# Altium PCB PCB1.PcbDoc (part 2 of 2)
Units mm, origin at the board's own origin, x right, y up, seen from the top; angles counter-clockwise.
Board outline 84 x 60 mm, 2 copper layers (Top Layer, Bottom Layer); 61 components, 46 nets, 218 pads, 307 vias.
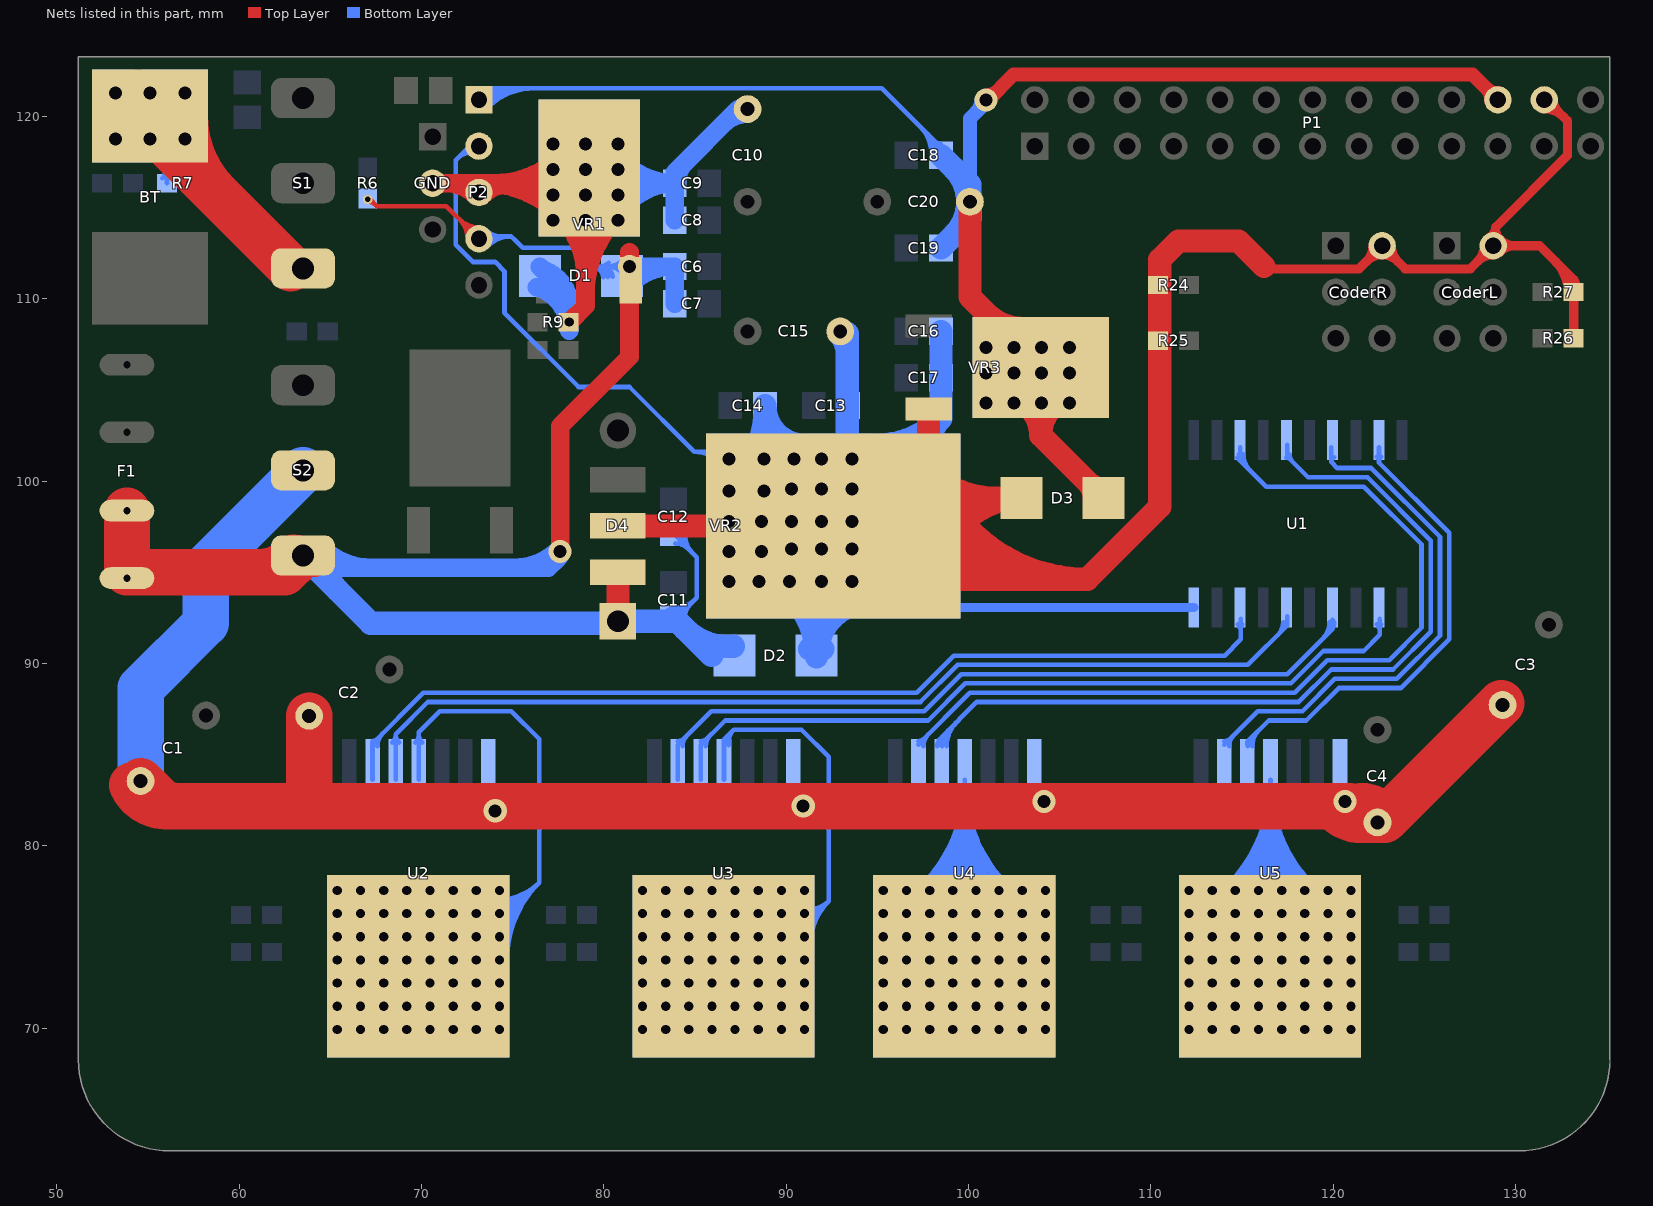
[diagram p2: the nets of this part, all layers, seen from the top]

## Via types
v1: diameter 0.762, hole 0.508, Top Layer to Bottom Layer, 224 vias
v2: diameter 1.27, hole 0.711, Top Layer to Bottom Layer, 75 vias
v3: diameter 0.559, hole 0.305, Top Layer to Bottom Layer, 3 vias
v4: diameter 0.508, hole 0.305, Top Layer to Bottom Layer, 3 vias
v5: diameter 1, hole 0.5, Top Layer to Bottom Layer, 2 vias

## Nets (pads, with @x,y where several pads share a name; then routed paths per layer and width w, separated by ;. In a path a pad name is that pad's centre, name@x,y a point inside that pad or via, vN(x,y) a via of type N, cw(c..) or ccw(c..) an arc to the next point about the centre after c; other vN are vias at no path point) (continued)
NetU1_3: U1.3 U4.2 | length 49.7
  Bottom Layer w0.254: U4.2@97.257,85.533 97.257,85.573 100.076,88.392 117.896,88.392 119.674,90.17 123.067,90.17 124.841,91.944 124.841,96.524 121.67,99.695 116.332,99.695 U1.3@114.745,101.282 ; U4.2@97.257,85.737 ccw(c97.257,86.133) U4.2@97.537,85.853 ; U4.2@97.53,85.464 cw(c98.451,85.464) 97.8,86.116 ; U1.3@114.811,101.458 ccw(c115.395,101.458) 114.982,101.045 ; U1.3@114.892,101.516 U1.3@114.892,101.854 ; U1.3@115.065,101.458 ccw(c116.262,101.458) 115.416,100.611
NetU1_5: U1.5 U4.3 | length 48.6
  Bottom Layer w0.254: U4.3@98.292,85.464 cw(c98.907,85.464) 98.472,85.899 ; U4.3@98.527,85.533 98.527,85.954 100.457,87.884 118.106,87.884 119.884,89.662 123.277,89.662 125.349,91.734 125.349,96.734 121.88,100.203 118.618,100.203 117.475,101.346 U1.5@117.475,101.981 ; U4.3@98.546,85.464 cw(c99.774,85.464) 98.905,86.332 ; U4.3@98.8,85.464 cw(c100.641,85.464) 99.339,86.766 ; U1.5@117.432,101.285 cw(c117.432,101.034) U1.5@117.61,101.211 ; U1.5@117.605,101.458 ccw(c118.189,101.458) 117.776,101.045
NetU1_7: U1.7 U5.2 | length 29.6
  Bottom Layer w0.254: U5.2@114.021,85.533 115.864,87.376 118.317,87.376 120.095,89.154 123.488,89.154 125.857,91.523 125.857,96.945 122.091,100.711 120.225,100.711 119.888,101.048 U1.7@119.888,101.854 ; U5.2@114.021,85.737 ccw(c114.021,86.23) 114.369,85.881 ; U5.2@114.294,85.464 cw(c115.119,85.464) 114.535,86.047 ; 119.888,101.04 cw(c120.184,101.04) U1.7@120.05,101.304
NetU1_9: U1.9 U5.3 | length 27.8
  Bottom Layer w0.254: U5.3@115.291,85.533 115.291,85.7 116.459,86.868 118.527,86.868 120.305,88.646 123.698,88.646 126.365,91.313 126.365,97.155 122.512,101.008 U1.9@122.512,101.854 ; U5.3@115.31,85.464 cw(c115.925,85.464) 115.49,85.899 ; U5.3@115.564,85.464 cw(c116.792,85.464) 115.923,86.332 ; U1.9@122.39,101.336 cw(c122.094,101.04) 122.512,101.04 cw(c122.93,101.04) U1.9@122.634,101.336
NetU1_12: U1.12 U3.3 | length 44.5
  Bottom Layer w0.254: U3.3@85.319,83.614 85.319,85.533 86.654,86.868 92.075,86.868 ; U3.3@85.319,85.737 ccw(c85.319,86.23) 85.667,85.881 ; U3.3@85.592,85.464 cw(c86.417,85.464) 85.833,86.047 ; 92.329,86.868 92.075,86.868 ; U1.12@122.39,92.136 cw(c121.991,91.737) 122.555,91.737 ; 122.555,91.944 cw(c122.826,91.944) U1.12@122.634,92.136 ; U1.12@122.555,92.456 122.555,91.567 121.666,90.678 119.463,90.678 117.685,88.9 99.818,88.9 97.786,86.868 92.075,86.868
NetU1_14: U1.14 U3.2 | length 43.8
  Bottom Layer w0.254: U3.2@84.049,83.614 84.049,85.533 85.892,87.376 91.059,87.376 ; U3.2@84.049,85.737 ccw(c84.049,86.23) 84.397,85.881 ; U3.2@84.322,85.464 cw(c85.147,85.464) 84.563,86.047 ; 91.313,87.376 91.059,87.376 ; 119.427,91.36 ccw(c118.529,92.258) U1.14@119.799,92.258 ; 119.861,91.794 ccw(c119.396,92.258) U1.14@120.053,92.258 ; U1.14@119.963,92.381 119.963,91.896 117.475,89.408 99.608,89.408 97.576,87.376 91.059,87.376
NetU1_16: U1.16 U2.3 | length 56.1
  Bottom Layer w0.254: U2.3@68.396,85.659 ccw(c67.952,86.113) 68.587,86.113 ; U2.3@68.587,83.614 68.587,86.113 ; U2.3@68.777,85.659 cw(c69.221,86.113) 68.587,86.113 ; 116.977,91.577 ccw(c116.296,92.258) U1.16@117.259,92.258 ; U1.16@117.475,92.583 117.475,92.075 115.316,89.916 99.397,89.916 97.365,87.884 70.358,87.884 68.587,86.113
NetU1_18: U1.18 U2.2 | length 54.8
  Bottom Layer w0.254: U2.2@67.317,83.614 67.317,85.605 70.104,88.392 97.155,88.392 99.187,90.424 114.046,90.424 114.935,91.313 U1.18@114.935,92.456 ; U2.2@67.317,85.737 ccw(c67.317,86.056) U2.2@67.542,85.83 ; U2.2@67.59,85.464 cw(c68.589,85.464) 67.882,86.17 ; U1.18@114.77,92.136 cw(c114.371,91.737) 114.935,91.737 ; 114.935,91.944 cw(c115.206,91.944) U1.18@115.014,92.136
NetU2_4: U2.0 U2.4 U2.8 | length 96.3
  Bottom Layer w0.254: U2.4@69.664,85.657 ccw(c69.213,86.107) 69.85,86.107 ; 69.85,86.139 ccw(c70.532,86.139) U2.4@70.05,85.657 ; U2.4@69.857,83.614 69.85,83.62 69.85,86.233 70.993,87.376 74.93,87.376 76.454,85.852 76.454,77.978 ; U2.8@71.202,75.578 ccw(c72.58,77.786) U2.8@74.421,75.945 ; U2.8@71.336,75.793 ccw(c72.754,78.064) U2.8@74.647,76.171 ; U2.8@71.471,76.009 ccw(c72.928,78.342) 74.873,76.397 ; U2.8@71.605,76.224 ccw(c73.101,78.62) 75.099,76.623 ; U2.8@71.74,76.44 ccw(c73.275,78.898) 75.325,76.849 ; U2.8@71.874,76.655 ccw(c73.449,79.176) 75.55,77.074 ; U2.8@72.009,76.87 ccw(c73.622,79.454) 75.776,77.3 ; U2.8@72.143,77.086 ccw(c73.796,79.732) 76.002,77.526 ; U2.8@72.278,77.301 ccw(c73.97,80.01) 76.228,77.752 ; U2.8@72.412,77.517 ccw(c74.143,80.288) 76.454,77.978 ; U2.8@72.517,74.041 76.454,77.978 ; U2.8@72.755,74.279 ccw(c72.439,74.595) U2.8@72.801,74.857 ; U2.8@72.965,74.489 ccw(c72.683,74.772) v1(73.006,75.006) ccw(c73.006,76.155) U2.8@73.819,75.343 ; U2.8@73.006,74.752 ccw(c73.006,75.288) U2.8@73.385,74.909 ; U2.8@73.006,75.26 ccw(c73.006,77.023) U2.8@74.252,75.776 ; U2.8@73.432,73.502 cw(c76.681,73.608) U2.8@74.382,75.906 ; U2.8@73.506,75.03 ccw(c72.26,76.276) U2.8@74.022,76.276 ; U2.8@73.686,73.51 cw(c77.483,73.635) U2.8@74.797,76.321 ; U2.8@73.94,73.518 cw(c78.285,73.661) 75.211,76.735 ; U2.8@73.94,75.464 ccw(c73.127,76.276) v1(74.276,76.276) ccw(c74.276,77.425) 75.089,76.613 ; U2.8@74.194,73.527 cw(c79.087,73.687) 75.625,77.149 ; U2.8@74.276,76.022 ccw(c74.276,76.558) U2.8@74.655,76.179 ; U2.8@74.276,76.53 ccw(c74.276,78.293) 75.522,77.046 ; U2.8@74.373,75.897 ccw(c73.994,76.276) U2.8@74.53,76.276 ; U2.8@74.448,73.535 cw(c79.889,73.714) 76.039,77.563 ; U2.8@74.702,73.543 cw(c80.692,73.74) 76.454,77.978
  other v1: 65.386,69.926 66.656,69.926 67.926,69.926 69.196,69.926 70.466,69.926 71.736,69.926 73.006,69.926 74.276,69.926 65.386,71.196 66.656,71.196 67.926,71.196 69.196,71.196 70.466,71.196 71.736,71.196 73.006,71.196 74.276,71.196 65.386,72.466 66.656,72.466 67.926,72.466 69.196,72.466 70.466,72.466 71.736,72.466 73.006,72.466 74.276,72.466 65.386,73.736 66.656,73.736 67.926,73.736 69.196,73.736 70.466,73.736 71.736,73.736 73.006,73.736 74.276,73.736 65.386,75.006 66.656,75.006 67.926,75.006 69.196,75.006 70.466,75.006 71.736,75.006 74.276,75.006 65.386,76.276 66.656,76.276 67.926,76.276 69.196,76.276 70.466,76.276 71.736,76.276 73.006,76.276 65.386,77.546 66.656,77.546 67.926,77.546 69.196,77.546 70.466,77.546 71.736,77.546 73.006,77.546 74.276,77.546
NetU3_4: U3.0 U3.4 U3.8 | length 70.7
  Bottom Layer w0.254: U3.4@86.589,83.614 86.589,85.827 87.122,86.36 ; U3.4@86.607,85.467 cw(c87.218,85.578) 86.779,86.017 ; U3.4@86.857,85.513 cw(c87.798,85.684) 87.122,86.36 ; U3.8@88.688,75.634 ccw(c89.844,76.859) U3.8@91.035,75.668 ; U3.8@88.862,75.819 ccw(c90.024,77.049) U3.8@91.22,75.853 ; U3.8@89.037,76.004 ccw(c90.203,77.239) U3.8@91.405,76.038 ; U3.8@89.211,76.188 ccw(c90.383,77.429) 91.589,76.222 ; U3.8@89.385,76.373 ccw(c90.562,77.62) 91.774,76.407 ; U3.8@89.56,76.558 ccw(c90.742,77.81) 91.959,76.592 ; U3.8@89.662,74.295 92.329,76.962 ; U3.8@89.734,76.742 ccw(c90.921,78) 92.144,76.777 ; U3.8@89.738,74.498 ccw(c89.738,74.805) U3.8@89.955,74.588 ; U3.8@89.738,74.752 ccw(c89.738,75.672) U3.8@90.389,75.022 ; v1(89.738,75.006) ccw(c89.738,76.539) U3.8@90.822,75.455 ; U3.8@89.738,75.26 ccw(c89.738,77.406) U3.8@91.256,75.889 ; U3.8@89.908,76.927 ccw(c91.101,78.19) 92.329,76.962 ; U3.8@89.924,74.557 cw(c91.008,73.473) v1(91.008,75.006) cw(c92.541,75.006) U3.8@91.457,76.09 ; U3.8@90.126,74.759 ccw(c88.608,76.276) U3.8@90.754,76.276 ; U3.8@90.358,74.991 cw(c91.008,74.34) U3.8@91.008,75.26 ; U3.8@90.5,75.006 cw(c90.807,75.006) U3.8@90.59,75.223 ; U3.8@90.559,75.192 ccw(c89.475,76.276) v1(91.008,76.276) ccw(c91.161,77.405) 91.966,76.599 ; U3.8@90.63,73.987 cw(c92.835,74.315) U3.8@91.259,75.892 ; U3.8@90.754,75.006 cw(c91.674,75.006) U3.8@91.024,75.657 ; U3.8@90.791,75.424 cw(c91.008,75.208) U3.8@91.008,75.514 ; U3.8@90.881,74.025 cw(c93.457,74.407) 91.615,76.248 ; U3.8@90.94,75.773 ccw(c90.988,76.128) U3.8@91.242,75.875 ; U3.8@90.974,76.025 ccw(c91.075,76.766) 91.604,76.237 ; U3.8@90.993,75.626 ccw(c90.342,76.276) U3.8@91.262,76.276 ; U3.8@91.042,76.528 ccw(c91.248,78.043) 92.329,76.962 ; U3.8@91.132,74.062 cw(c94.078,74.499) 91.972,76.605 ; U3.8@91.262,75.006 cw(c93.408,75.006) 91.891,76.524 ; U3.8@91.383,74.099 cw(c94.699,74.592) 92.329,76.962 ; U3.8@91.426,76.059 ccw(c91.21,76.276) U3.8@91.516,76.276 ; 87.122,86.36 90.841,86.36 92.329,84.872 92.329,76.962
  other v1: 82.118,69.926 83.388,69.926 84.658,69.926 85.928,69.926 87.198,69.926 88.468,69.926 89.738,69.926 91.008,69.926 82.118,71.196 83.388,71.196 84.658,71.196 85.928,71.196 87.198,71.196 88.468,71.196 89.738,71.196 91.008,71.196 82.118,72.466 83.388,72.466 84.658,72.466 85.928,72.466 87.198,72.466 88.468,72.466 89.738,72.466 91.008,72.466 82.118,73.736 83.388,73.736 84.658,73.736 85.928,73.736 87.198,73.736 88.468,73.736 89.738,73.736 91.008,73.736 82.118,75.006 83.388,75.006 84.658,75.006 85.928,75.006 87.198,75.006 88.468,75.006 82.118,76.276 83.388,76.276 84.658,76.276 85.928,76.276 87.198,76.276 88.468,76.276 89.738,76.276 82.118,77.546 83.388,77.546 84.658,77.546 85.928,77.546 87.198,77.546 88.468,77.546 89.738,77.546 91.008,77.546
NetU4_4: U4.0 U4.4 U4.8 | length 121.8
  Bottom Layer w0.254: U4.8@96.716,77.18 ccw(c91.539,83.613) U4.4@99.797,83.614 ccw(c108.141,83.613) U4.8@102.857,77.155 ; U4.8@96.875,76.982 ccw(c91.966,83.083) U4.4@99.797,83.083 ; U4.8@97.035,76.784 ccw(c92.392,82.552) U4.4@99.797,82.552 ; U4.8@97.194,76.586 ccw(c92.819,82.022) U4.4@99.797,82.022 ; U4.8@97.353,76.388 ccw(c93.246,81.492) U4.4@99.797,81.492 ; U4.8@97.512,76.191 ccw(c93.673,80.961) 99.797,80.961 ; U4.8@97.672,75.993 ccw(c94.1,80.431) 99.797,80.431 ; U4.8@97.831,75.795 ccw(c94.527,79.9) 99.797,79.9 ; U4.8@97.99,75.597 ccw(c94.954,79.37) 99.797,79.37 ; U4.8@98.149,75.399 ccw(c95.381,78.839) 99.797,78.839 ; U4.4@99.604,81.571 cw(c99.138,81.105) 99.797,81.105 cw(c100.456,81.105) U4.4@99.99,81.571 ; 99.797,78.789 ccw(c104.194,78.789) U4.8@101.409,75.386 ; 99.797,79.325 ccw(c104.633,79.325) U4.8@101.57,75.582 ; 99.797,79.861 ccw(c105.071,79.861) U4.8@101.731,75.779 ; 99.797,80.397 ccw(c105.51,80.397) U4.8@101.892,75.976 ; 99.797,80.933 ccw(c105.948,80.933) U4.8@102.053,76.172 ; U4.4@99.797,81.469 ccw(c106.387,81.469) U4.8@102.214,76.369 ; U4.4@99.797,82.005 ccw(c106.825,82.005) U4.8@102.374,76.565 ; U4.4@99.797,82.541 ccw(c107.264,82.541) U4.8@102.535,76.762 ; U4.4@99.797,83.077 ccw(c107.703,83.077) U4.8@102.696,76.958 ; U4.4@99.797,83.614 99.797,75.844 U4.8@99.822,75.819
  other v1: 95.326,69.926 96.596,69.926 97.866,69.926 99.136,69.926 100.406,69.926 101.676,69.926 102.946,69.926 104.216,69.926 95.326,71.196 96.596,71.196 97.866,71.196 99.136,71.196 100.406,71.196 101.676,71.196 102.946,71.196 104.216,71.196 95.326,72.466 96.596,72.466 97.866,72.466 99.136,72.466 100.406,72.466 101.676,72.466 102.946,72.466 104.216,72.466 95.326,73.736 96.596,73.736 97.866,73.736 99.136,73.736 100.406,73.736 101.676,73.736 102.946,73.736 104.216,73.736 95.326,75.006 96.596,75.006 97.866,75.006 99.136,75.006 100.406,75.006 101.676,75.006 102.946,75.006 104.216,75.006 95.326,76.276 96.596,76.276 97.866,76.276 99.136,76.276 100.406,76.276 101.676,76.276 102.946,76.276 104.216,76.276 95.326,77.546 96.596,77.546 97.866,77.546 99.136,77.546 100.406,77.546 101.676,77.546 102.946,77.546 104.216,77.546
NetU5_4: U5.0 U5.4 U5.8 | length 122.2
  Bottom Layer w0.254: U5.8@113.48,77.18 ccw(c108.303,83.613) U5.4@116.561,83.614 ccw(c124.905,83.613) U5.8@119.621,77.155 ; U5.8@113.639,76.982 ccw(c108.73,83.083) U5.4@116.561,83.083 ; U5.8@113.799,76.784 ccw(c109.156,82.552) U5.4@116.561,82.552 ; U5.8@113.958,76.586 ccw(c109.583,82.022) U5.4@116.561,82.022 ; U5.8@114.117,76.388 ccw(c110.01,81.492) U5.4@116.561,81.492 ; U5.8@114.276,76.191 ccw(c110.437,80.961) 116.561,80.961 ; U5.8@114.436,75.993 ccw(c110.864,80.431) 116.561,80.431 ; U5.8@114.595,75.795 ccw(c111.291,79.9) 116.561,79.9 ; U5.8@114.754,75.597 ccw(c111.718,79.37) 116.561,79.37 ; U5.8@114.913,75.399 ccw(c112.145,78.839) 116.561,78.839 ; U5.4@116.368,81.571 cw(c115.902,81.105) 116.561,81.105 cw(c117.22,81.105) U5.4@116.754,81.571 ; U5.8@116.561,75.463 U5.4@116.561,83.614 ; 116.561,78.789 ccw(c120.958,78.789) U5.8@118.173,75.386 ; 116.561,79.325 ccw(c121.397,79.325) U5.8@118.334,75.582 ; 116.561,79.861 ccw(c121.835,79.861) U5.8@118.495,75.779 ; 116.561,80.397 ccw(c122.274,80.397) U5.8@118.656,75.976 ; 116.561,80.933 ccw(c122.712,80.933) U5.8@118.817,76.172 ; U5.4@116.561,81.469 ccw(c123.151,81.469) U5.8@118.978,76.369 ; U5.4@116.561,82.005 ccw(c123.589,82.005) U5.8@119.138,76.565 ; U5.4@116.561,82.541 ccw(c124.028,82.541) U5.8@119.299,76.762 ; U5.4@116.561,83.077 ccw(c124.467,83.077) U5.8@119.46,76.958
  other v1: 112.09,69.926 113.36,69.926 114.63,69.926 115.9,69.926 117.17,69.926 118.44,69.926 119.71,69.926 120.98,69.926 112.09,71.196 113.36,71.196 114.63,71.196 115.9,71.196 117.17,71.196 118.44,71.196 119.71,71.196 120.98,71.196 112.09,72.466 113.36,72.466 114.63,72.466 115.9,72.466 117.17,72.466 118.44,72.466 119.71,72.466 120.98,72.466 112.09,73.736 113.36,73.736 114.63,73.736 115.9,73.736 117.17,73.736 118.44,73.736 119.71,73.736 120.98,73.736 112.09,75.006 113.36,75.006 114.63,75.006 115.9,75.006 117.17,75.006 118.44,75.006 119.71,75.006 120.98,75.006 112.09,76.276 113.36,76.276 114.63,76.276 115.9,76.276 117.17,76.276 118.44,76.276 119.71,76.276 120.98,76.276 112.09,77.546 113.36,77.546 114.63,77.546 115.9,77.546 117.17,77.546 118.44,77.546 119.71,77.546 120.98,77.546
VCC: C13.2 C14.2 C15.1 C16.2 C17.2 CoderL.2 CoderR.2 D2.1 D3.2 P1.25 P2.2 R24.2 R25.2 R26.2 R27.2 U1.20 VR2.2 VR3.3 | length 345.5
  Top Layer w0.254: CoderL.2@128.79,112.891 CoderL.2@128.778,112.903 CoderL.2@128.905,112.903
  Top Layer w0.508: 116.071,111.633 121.412,111.633 CoderR.2@122.682,112.903 123.952,111.633 127.508,111.633 CoderL.2@128.778,112.903 ; CoderR.2@122.186,112.903 cw(c120.989,112.903) 121.835,112.056 cw(c122.682,111.21) 122.682,112.407 cw(c122.682,111.21) 123.529,112.056 cw(c124.375,112.903) CoderR.2@123.178,112.903 ; CoderL.2@128.282,112.903 cw(c127.085,112.903) 127.931,112.056 cw(c128.778,111.21) CoderL.2@128.778,112.407 ; CoderL.2@128.554,113.345 ccw(c128.263,113.918) 128.905,113.918 ; 128.905,113.794 ccw(c129.669,113.794) 129.129,113.254 ccw(c129.975,114.1) 129.975,112.903 ccw(c129.975,111.706) CoderL.2@129.129,112.552 ; P1.25@131.572,120.408 cw(c131.572,118.904) 132.636,119.967 ; P1.25@131.572,120.904 131.699,120.904 132.842,119.761 132.842,117.855 128.905,113.918 ; P1.25@132.068,120.904 ccw(c132.959,120.904) 132.329,120.274 ; 132.202,112.019 cw(c130.546,110.363) R27.2@132.888,110.363 ; R26.2@133.01,107.997 ccw(c132.59,108.417) 133.184,108.417 ccw(c133.778,108.417) R26.2@133.358,107.997 ; R27.2@133.01,110.189 cw(c132.59,109.769) 133.184,109.769 cw(c133.778,109.769) R27.2@133.358,110.189 ; R27.2@133.01,110.537 ccw(c132.59,110.957) 133.184,110.957 ccw(c133.778,110.957) R27.2@133.358,110.537 ; 133.069,111.152 cw(c132.281,110.363) R27.2@133.396,110.363 ; R26.2@133.184,107.823 133.184,111.037 131.318,112.903 128.905,112.903 128.905,113.918
  Top Layer w1.27: VR2.2@80.772,97.536 VR2.2@92.583,97.536 ; VR2.2@86.255,97.536 ccw(c86.255,98.403) v2(86.868,97.79) ccw(c87.481,98.403) VR2.2@87.481,97.536 ; VR2.2@87.231,97.536 cw(c87.231,93.2) v2(90.297,96.266) cw(c92.583,94.844) VR2.2@92.583,97.536 ; VR2.2@88.033,97.536 ccw(c88.033,98.403) v2(88.646,97.79) ccw(c89.259,98.403) VR2.2@89.259,97.536 ; VR2.2@88.882,97.536 cw(c88.882,93.2) v2(91.948,96.266) ; VR2.2@89.684,97.536 ccw(c89.684,98.403) v2(90.297,97.79) ccw(c90.91,98.403) VR2.2@90.91,97.536 ; VR2.2@91.335,97.536 ccw(c91.335,98.403) v2(91.948,97.79) cw(c91.948,96.87) VR2.2@92.598,97.521 ; v2(93.599,99.568) ccw(c94.825,100.794) VR2.2@94.825,99.06 ; VR2.2@94.107,99.06 D3.2@102.906,99.06 ccw(c102.906,94.585) VR2.2@98.683,96.065 ; VR2.2@94.497,95.622 cw(c96.665,97.79) v2(93.599,97.79) ; VR2.2@95.054,97.825 ccw(c100.296,100.5) 100.296,94.615 ; VR2.2@96.185,98.402 ccw(c102.37,101.559) 102.37,94.615 ; VR2.2@97.316,98.979 ccw(c104.444,102.618) 104.444,94.615 ; VR2.2@97.484,96.486 cw(c101.115,95.213) 101.115,99.06 ; VR2.2@97.631,100.679 ccw(c101.54,104.588) 101.54,99.06 ; VR2.2@97.808,100.838 VR3.3@97.808,103.943 ; VR2.2@98.447,99.557 ccw(c106.518,103.676) 106.518,94.615 ; D3.2@102.542,98.696 ccw(c101.663,97.817) 101.663,99.06 ccw(c101.663,100.303) D3.2@102.542,99.424 ; 116.205,111.76 114.808,113.157 111.506,113.157 110.49,112.141 110.49,98.587 106.518,94.615 95.504,94.615 VR2.2@92.583,97.536 ; v2(93.599,97.79) cw(c92.986,98.403) 92.986,97.536 ccw(c92.986,98.403) v2(93.599,97.79)
  Bottom Layer w0.254: 71.882,113.336 71.882,113.538 ; 71.956,117.676 cw(c72.814,116.819) P2.2@73.073,118.004 ; 72.285,118.005 cw(c72.932,117.358) P2.2@73.127,118.252 ; P2.2@73.152,118.872 71.882,117.602 71.882,113.538 ; 85.507,101.6 cw(c85.507,100.079) VR2.2@86.673,101.056 ; VR2.2@86.052,101.6 cw(c86.052,100.535) v2(86.868,101.219) cw(c87.788,100.299) VR2.2@87.788,101.6 ; VR2.2@86.479,100.893 ccw(c84.963,99.623) 84.963,101.6 ; VR2.2@86.627,101.6 cw(c86.627,99.073) VR2.2@88.414,100.86 ; VR2.2@87.048,101.039 cw(c88.401,99.686) VR2.2@88.401,101.6 ; VR2.2@87.227,100.86 cw(c89.014,99.073) VR2.2@89.014,101.6 ; VR2.2@87.24,101.6 cw(c87.24,99.686) VR2.2@88.593,101.039 ; VR2.2@87.853,101.6 cw(c87.853,100.299) v2(88.773,101.219) cw(c89.693,100.299) VR2.2@89.693,101.6 ; VR2.2@88.278,101.6 cw(c88.278,99.073) VR2.2@90.065,100.86 ; VR2.2@88.891,101.6 cw(c88.891,99.686) VR2.2@90.244,101.039 ; VR2.2@88.953,101.039 cw(c90.306,99.686) VR2.2@90.306,101.6 ; VR2.2@89.132,100.86 cw(c90.919,99.073) VR2.2@90.919,101.6 ; VR2.2@89.504,101.6 cw(c89.504,100.299) v2(90.424,101.219) cw(c91.132,100.753) VR2.2@91.132,101.6 ; VR2.2@89.802,101.6 cw(c89.802,99.073) VR2.2@91.589,100.86 ; VR2.2@90.415,101.6 cw(c90.415,99.686) VR2.2@91.768,101.039 ; VR2.2@90.636,101.079 cw(c91.603,100.442) VR2.2@91.603,101.6 ; VR2.2@90.848,100.939 cw(c92.075,100.131) 92.075,101.6 84.963,101.6 ; VR2.2@91.028,101.6 cw(c91.028,100.299) v2(91.948,101.219) ; 71.882,113.538 71.882,112.955 72.823,112.014 74.041,112.014 74.549,111.506 74.549,109.22 78.613,105.156 81.407,105.156 84.963,101.6
  Bottom Layer w0.508: VR2.2@98.585,93.058 U1.20@112.352,93.058
  Bottom Layer w1.27: VR2.2@87.535,100.679 ccw(c84.399,103.815) C14.2@88.834,103.815 ; VR2.2@88.834,101.666 C14.2@88.834,104.14 ccw(c91.001,104.14) VR2.2@90.895,101.976 ; 88.834,102.806 ccw(c90.936,102.806) VR2.2@90.833,100.707 ; VR2.2@89.864,94.02 cw(c87.037,90.364) 91.658,90.364 cw(c94.687,90.364) VR2.2@93.834,93.271 ; D2.1@91.294,90.788 ccw(c90.415,91.667) 91.658,91.667 ccw(c92.901,91.667) D2.1@92.022,90.788 ; D2.1@91.658,90.424 VR2.2@91.658,96.611 ; 91.658,92.06 cw(c94.189,92.06) VR2.2@93.477,94.489 ; VR2.2@91.658,93.788 cw(c92.648,93.788) v2(91.948,94.488) cw(c92.648,95.188) VR2.2@91.658,95.188 ; VR2.2@91.658,95.566 cw(c92.648,95.566) v2(91.948,96.266) ; VR2.2@92.298,97.251 cw(c93.599,95.95) v2(93.599,97.79) ; VR2.2@92.583,97.536 98.486,103.439 ; C15.1@92.874,108.114 cw(c91.738,106.978) 93.345,106.978 ; VR2.2@93.091,98.044 ccw(c91.821,99.314) v2(93.599,99.568) ; VR2.2@93.345,97.79 C15.1@93.345,108.077 ; VR2.2@93.345,98.403 ccw(c94.212,98.403) v2(93.599,97.79) ; VR2.2@93.345,98.955 cw(c94.212,98.955) v2(93.599,99.568) ; VR2.2@93.345,100.181 ccw(c94.212,100.181) v2(93.599,99.568) ; VR2.2@93.345,100.606 cw(c94.212,100.606) v2(93.599,101.219) cw(c94.212,101.832) VR2.2@93.345,101.832 ; VR2.2@93.466,98.419 cw(c91.948,99.936) v2(91.948,97.79) ; VR2.2@94.138,99.091 ccw(c95.439,97.79) v2(93.599,97.79) ; VR2.2@94.701,101.976 ccw(c94.94,106.984) 98.486,103.439 ; VR2.2@95.333,100.286 cw(c93.599,102.021) v2(93.599,99.568) ; VR2.2@97.114,99.321 cw(c99.09,100.664) VR2.2@97.4,102.353 ; VR2.2@98.164,100.035 cw(c100.382,101.542) 98.486,103.439 ; C16.2@98.486,108.204 C17.2@98.486,105.664 98.486,103.439 ; v2(91.948,97.79) ccw(c92.648,97.09) 91.658,97.09 cw(c92.648,97.09) v2(91.948,97.79)
  other v2: 86.868,94.488 88.519,94.488 90.17,94.488 93.599,94.488 86.868,96.139 88.646,96.139 93.599,96.266 86.868,99.441 88.773,99.441 90.297,99.568 91.948,99.568
VCC_3V3: C18.2 C19.2 C20.1 D3.1 P1.24 P2.1 VR3.2 | length 130.6
  Top Layer w0.762: v2@100.901,120.84 101.028,120.84 102.477,122.289 127.647,122.289 P1.24@129.032,120.904 ; v2@100.965,121.158 ccw(c100.965,122.078) 101.615,121.427 ; P1.24@128.663,120.904 ccw(c127.772,120.904) 128.402,121.534 ccw(c129.032,122.164) P1.24@129.032,121.273
  Top Layer w1.27: C20.1@99.949,115.316 100.076,115.189 100.076,110.105 VR3.2@103.958,106.223 103.958,102.508 ; 100.994,109.187 ccw(c102.983,111.175) VR3.2@102.983,108.363 ; VR3.2@101.235,108.946 cw(c98.207,105.918) v2(102.489,105.918) ; VR3.2@101.331,108.85 cw(c99.319,106.838) VR3.2@102.125,106.367 ; VR3.2@102.055,108.126 ccw(c104.013,110.085) v2(104.013,107.315) cw(c103.674,109.16) VR3.2@102.347,107.834 ; VR3.2@102.223,107.958 cw(c101.579,107.315) v2(102.489,107.315) cw(c102.489,106.405) VR3.2@103.132,107.049 ; VR3.2@102.885,104.372 cw(c101.804,102.508) 103.958,102.508 ; VR3.2@105.031,104.372 ccw(c106.112,102.508) 103.958,102.508 ; D3.1@106.891,99.06 ccw(c105.648,99.06) 106.527,99.939 ccw(c107.406,100.818) D3.1@107.406,99.575 ; D3.1@107.406,99.06 103.958,102.508
  Bottom Layer w0.254: P2.1@72.874,121.182 cw(c73.736,120.32) P2.1@73.736,121.539 ; P2.1@73.054,121.002 cw(c74.349,119.707) 74.349,121.539 ; P2.1@73.152,121.412 73.279,121.539 95.25,121.539 C18.2@98.806,117.983 ; P2.1@73.233,120.823 cw(c74.963,119.093) 74.963,121.539 ; P2.1@73.413,120.643 cw(c75.576,118.48) 75.576,121.539 ; P2.1@73.593,120.463 cw(c76.189,117.867) 76.189,121.539 ; 97.348,119.441 cw(c95.863,117.956) C18.2@97.963,117.956 ; 97.781,119.008 cw(c96.73,117.956) C18.2@98.217,117.956 ; C18.2@98.186,118.603 ccw(c98.486,118.904) C18.2@98.486,118.479 ; C18.2@98.215,118.574 cw(c97.597,117.956) C18.2@98.471,117.956
  Bottom Layer w0.762: 100.076,116.266 100.076,119.888 v2@101.028,120.84 ; 100.442,120.254 ccw(c99.791,120.904) v2@100.711,120.904 ; 100.076,116.236 cw(c99.156,116.236) 99.807,115.585 ccw(c99.156,116.236) 100.076,116.236 ; 100.076,116.236 ccw(c100.996,116.236) 100.345,115.585 cw(c100.996,116.236) 100.076,116.236
  Bottom Layer w1.27: C19.2@98.486,112.776 100.076,114.366 C20.1@100.076,115.316 100.076,116.266 C18.2@98.486,117.856 ; 99.187,113.477 ccw(c97.349,115.316) 99.949,115.316 ccw(c97.349,115.316) 99.187,117.155
  other v2: 100.965,104.267 102.489,104.267 104.013,104.267 105.537,104.267 100.965,105.918 104.013,105.918 105.537,105.918 100.965,107.315 105.537,107.315 100.965,120.904
VCC_ADJ: C8.2 C9.2 C10.1 D1.1 GND.2 P2.3 R9.2 VR1.2 | length 86.6
  Top Layer w1.016: GND.2@70.612,116.332 76.839,116.332 78.994,114.177 78.994,109.601 v5(78.105,108.712) ; GND.2@71.341,116.332 cw(c71.341,114.013) P2.3@72.981,115.653 ; P2.3@73.323,115.653 cw(c74.963,114.013) 74.963,116.332 ; P2.3@73.384,116.332 cw(c73.384,110.378) 77.594,114.588 cw(c74.215,111.209) 78.994,111.209 ; 74.065,116.332 ccw(c74.065,121.324) VR1.2@77.594,117.794 ; 75.07,116.332 ccw(c75.07,119.24) VR1.2@77.126,117.184 ; 75.376,116.332 cw(c75.376,113.857) VR1.2@77.126,115.607 ; 75.837,116.332 cw(c75.837,112.83) VR1.2@78.313,115.306 ; VR1.2@76.715,116.456 ccw(c77.274,117.016) VR1.2@77.748,116.381 ; VR1.2@77.216,115.57 cw(c77.216,114.64) VR1.2@77.874,115.298 ; VR1.2@77.343,117.094 ccw(c80.399,117.094) VR1.2@78.238,114.933 ; 78.994,110.227 cw(c85.161,110.227) VR1.2@80.8,114.588 ; 78.994,112.68 cw(c82.708,112.68) VR1.2@80.082,115.306
  Bottom Layer w1.016: D1.1@76.31,110.636 cw(c75.612,108.242) v5@78.105,108.242 ; D1.1@76.49,111.76 78.105,110.145 v5(78.105,108.712) ; D1.1@76.516,110.611 cw(c76.617,108.149) 78.359,109.891 ; D1.1@76.595,111.611 cw(c76.007,109.597) 78.105,109.597 ; VR1.2@80.143,116.326 cw(c80.159,116.31) VR1.2@80.159,116.332 ; VR1.2@80.143,116.465 ccw(c80.465,116.787) VR1.2@80.465,116.332 ; VR1.2@80.493,116.332 C9.2@83.886,116.332 ; VR1.2@80.862,115.607 cw(c82.612,113.857) 82.612,116.332 ; VR1.2@80.862,117.184 ccw(c82.918,119.24) 82.918,116.332 ; VR1.2@80.905,117.686 ccw(c83.886,120.29) C9.2@83.886,116.332 ; VR1.2@81.038,114.872 cw(c83.886,112.825) C9.2@83.886,116.332 ; C8.2@83.886,114.3 C9.2@83.886,116.332 ; C9.2@84.028,116.432 cw(c85.524,116.432) 84.466,117.49 ; 86.577,119.601 cw(c87.884,118.294) C10.1@87.884,120.142 ; C10.1@87.372,120.396 83.886,116.91 C9.2@83.886,116.332
  other v2: 77.216,114.3 78.994,114.3 80.772,114.3 77.216,115.697 78.994,115.697 80.772,115.697 77.216,117.094 78.994,117.094 80.772,117.094 77.216,118.491 78.994,118.491 80.772,118.491
VCC_BAT: BT.1 R7.2 S1.1 | length 38.2
  Top Layer w0.254: S1.1@62.836,111.662 S1.1@63.5,111.662 S1.1@62.963,111.125
  Top Layer w2.54: BT.1@54.483,121.285 ccw(c57.549,121.285) BT.1@55.381,119.117 ; BT.1@55.118,120.015 55.118,119.38 S1.1@62.836,111.662 ; BT.1@55.939,118.559 ccw(c57.023,119.643) BT.1@57.023,118.11 ; BT.1@56.388,118.745 ccw(c57.921,118.745) BT.1@56.837,117.661 ; BT.1@57.023,120.015 ccw(c63.155,120.015) 58.819,115.679
  Bottom Layer w0.254: BT.1@55.025,117.714 cw(c54.584,116.32) 56.046,116.32 cw(c57.912,116.321) BT.1@56.971,117.932 ; BT.1@55.102,117.957 cw(c54.694,116.667) R7.2@56.046,116.667 ; BT.1@55.178,118.199 cw(c54.803,117.014) 56.046,117.014 ; BT.1@55.255,118.441 cw(c54.913,117.361) 56.046,117.361 ; R7.2@55.782,116.596 ccw(c55.146,117.232) 56.046,117.232 ccw(c56.946,117.232) R7.2@56.31,116.596 ; BT.1@56.007,118.872 56.046,118.833 R7.2@56.046,116.332 ; R7.2@56.046,116.763 cw(c57.653,116.763) BT.1@56.842,118.151 ; 56.046,117.206 cw(c57.395,117.206) BT.1@56.714,118.37
  other v2: 53.213,118.745 55.118,118.745 57.023,118.745 53.213,121.285 55.118,121.285 57.023,121.285
VCC_MOTOR: C1.1 C2.1 C3.1 C4.1 S2.2 U2.7 U3.7 U4.7 U5.7 | length 114.6
  Top Layer w2.54: C1.1@54.133,83.33 ccw(c55.971,84.204) 55.971,82.169 ; C1.1@54.233,83.189 ccw(c56.695,85.651) 56.695,82.169 ; C1.1@54.592,83.548 55.971,82.169 ; 63.246,82.169 63.754,82.169 ; C2.1@63.84,87.122 63.84,82.464 63.881,82.423 ; C3.1@129.222,87.82 122.809,81.407 121.666,81.407 120.904,82.169 v2(90.932,82.169) 63.754,82.169 ; 55.971,82.169 63.754,82.169 ; 120.201,81.974 ccw(c121.57,83.343) 121.57,81.407 cw(c121.57,83.343) 120.201,81.974 ; 121.508,82.169 cw(c121.508,80.36) 122.787,81.639 ccw(c121.508,80.36) 121.508,82.169
  Bottom Layer w2.54: C1.1@54.61,83.947 54.61,88.646 58.166,92.202 58.166,95.263 63.487,100.584 S2.2@63.5,100.584
  other v2: 74.041,81.915 104.14,82.423 120.65,82.423
VCC_POWER: C6.2 C7.2 C11.2 C12.2 D1.2 D2.2 D4.2 F1.2 P2.4 R6.2 S2.1 VR1.3 VR2.3 | length 134
  Top Layer w0.254: v4@67.056,115.316 cw(c67.056,114.703) 67.49,115.136 ; v4@67.183,115.443 67.555,115.071 71.365,115.071 72.644,113.792 P2.4@73.152,113.792 ; P2.4@72.529,113.284 ccw(c71.025,113.284) 72.088,114.348 ccw(c73.152,115.411) P2.4@73.152,113.907 ; P2.4@72.783,113.284 ccw(c71.892,113.284) 72.522,113.914 ccw(c73.152,114.544) P2.4@73.152,113.653
  Top Layer w1.016: S2.1@63.5,95.914 S2.1@64.164,95.25 ; v2@77.597,96.266 77.597,102.997 81.407,106.807 81.407,112.54
  Top Layer w1.27: D4.2@80.772,92.306 VR2.3@80.772,94.996
  Top Layer w2.54: F1.2@53.848,98.374 53.848,94.996 62.484,94.996 S2.1@63.246,95.758 ; 61.044,94.996 ccw(c61.044,97.72) S2.1@62.97,95.794
  Bottom Layer w0.254: P2.4@73.152,113.792 73.533,113.411 74.93,113.411 ; P2.4@73.416,113.026 cw(c74.328,112.138) 74.328,113.411 ; P2.4@73.593,113.725 ccw(c74.349,114.481) 74.349,113.411 ; P2.4@73.598,112.849 cw(c74.93,111.552) 74.93,113.411 ; 79.604,111.76 cw(c79.604,111.139) D1.2@80.224,111.189 ; 79.747,111.76 ccw(c79.747,112.495) D1.2@80.267,111.975 ; D1.2@79.88,111.76 cw(c79.88,111.161) D1.2@80.477,111.21 ; D1.2@79.97,111.169 ccw(c79.329,111.116) 79.329,111.76 ; D1.2@81.048,111.401 ccw(c80.181,110.534) 80.181,111.76 ccw(c80.181,112.986) D1.2@81.048,112.119 ; v2(81.407,111.76) 79.329,111.76 ; C11.2@83.82,92.522 C11.2@84.013,92.522 ; C12.2@83.82,97.094 85.09,95.824 85.09,93.599 C11.2@84.013,92.522 ; C11.2@83.92,92.791 ccw(c83.92,93.665) C11.2@84.538,93.047 ; C11.2@83.92,93.045 ccw(c83.92,94.532) 84.972,93.481 ; C12.2@83.92,96.571 cw(c83.92,95.55) 84.642,96.272 ; C11.2@83.947,92.456 C11.2@84.013,92.522 ; C12.2@84.189,97.094 ccw(c85.08,97.094) C12.2@84.45,96.464 ; C11.2@84.275,92.522 C11.2@84.013,92.522 ; C11.2@84.443,92.522 cw(c85.481,92.522) 84.747,93.256 ; C12.2@84.443,97.094 ccw(c85.947,97.094) 84.884,96.03 ; 74.93,113.411 75.116,113.225 75.558,112.783 78.306,112.783 79.329,111.76
  Bottom Layer w1.016: S2.1@64.164,95.25 76.962,95.25 v2@77.534,95.822 ; S2.1@64.569,96.333 ccw(c67.182,98.946) 67.182,95.25 ; 75.144,95.25 ccw(c75.144,98.592) v2@77.507,96.229 ; 77.201,95.489 ccw(c76.55,96.139) v2@77.47,96.139 ; v2(81.407,111.76) C6.2@83.886,111.76 C7.2@83.886,109.728 ; D1.2@81.444,110.798 cw(c83.766,108.476) C6.2@83.766,111.76
  Bottom Layer w1.27: S2.1@64.164,95.25 67.212,92.202 D4.2@81.026,92.202 ; S2.1@64.615,95.914 ccw(c67.307,95.914) 65.403,94.011 ; 79.64,92.202 ccw(c79.64,93.438) D4.2@80.514,92.564 ; D4.2@80.772,92.306 C11.2@83.947,92.306 ; C11.2@83.82,92.522 85.918,90.424 ; C11.2@84.44,91.902 ccw(c86.804,94.266) D2.2@87.111,90.937
  other v2: 77.597,96.139
  other v4: 67.056,115.443
pads on no net: CoderL.5 CoderL.6 CoderR.5 CoderR.6 P1.8 P1.9 P1.13 P1.18 P1.21 P1.22 P1.23 P1.26 S1.3 S2.3

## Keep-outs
Keep-Out Layer:
  circle w0.127: c130.179,71.956 r1.5
  circle w0.127: c56.179,71.956 r1.5
  lines w0.127: 51.179,68.26 ccw(c56.179,68.26) 56.179,63.26 130.179,63.26 ccw(c130.179,68.26) 135.179,68.26 135.179,123.26 51.179,123.26 51.179,68.26

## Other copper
Top Layer:
  rectangle net VCC: 85.217,86.995 111.76,97.409
  rectangle net VCC: 84.963,86.995 100.965,102.489
  rectangle net NetU2_4: 58.547,68.326 74.93,80.137
  rectangle net NetU3_4: 75.311,68.326 91.694,80.137
  rectangle net NetU4_4: 94.615,68.326 110.998,80.137
  rectangle net NetU5_4: 111.379,68.326 127.762,79.756
  text "2017北华航天工业学院摄像头队" at 68.326,64.008 h3.81
Bottom Layer:
  rectangle net VCC_3V3: 100.203,94.869 109.22,109.474
  rectangle net GND: 64.897,81.407 66.548,87.503
  rectangle net VCC_MOTOR: 73.152,81.026 75.565,86.106
  rectangle net GND: 79.629,81.407 83.185,87.503
  rectangle net VCC_MOTOR: 90.043,81.407 91.948,84.709
  rectangle net GND: 92.71,81.407 96.393,86.487
  rectangle net VCC_MOTOR: 103.251,81.407 106.426,86.741
  rectangle net GND: 109.982,81.407 113.157,86.741
  rectangle net VCC_MOTOR: 120.015,81.407 121.412,86.741

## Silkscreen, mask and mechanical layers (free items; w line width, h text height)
Top Paste:
  text "2017北华航天工业学院摄像头队" at 68.326,64.008 h3.81
Top Solder:
  rectangle: 85.217,86.995 111.76,97.409
  rectangle: 84.963,86.995 100.965,102.489
  rectangle: 111.379,68.326 127.762,79.756
  rectangle: 94.615,68.326 110.998,80.137
  rectangle: 75.311,68.326 91.694,80.137
  rectangle: 58.547,68.326 74.93,80.137
  lines w0.254: 57.023,82.296 57.15,82.169
  lines w2.54: 57.15,82.169 119.507,82.169 ; 66.675,85.471 122.936,85.471
  text "2017北华航天工业学院摄像头队" at 68.326,64.008 h3.81
Bottom Solder:
  rectangle: 100.203,94.869 109.22,109.474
